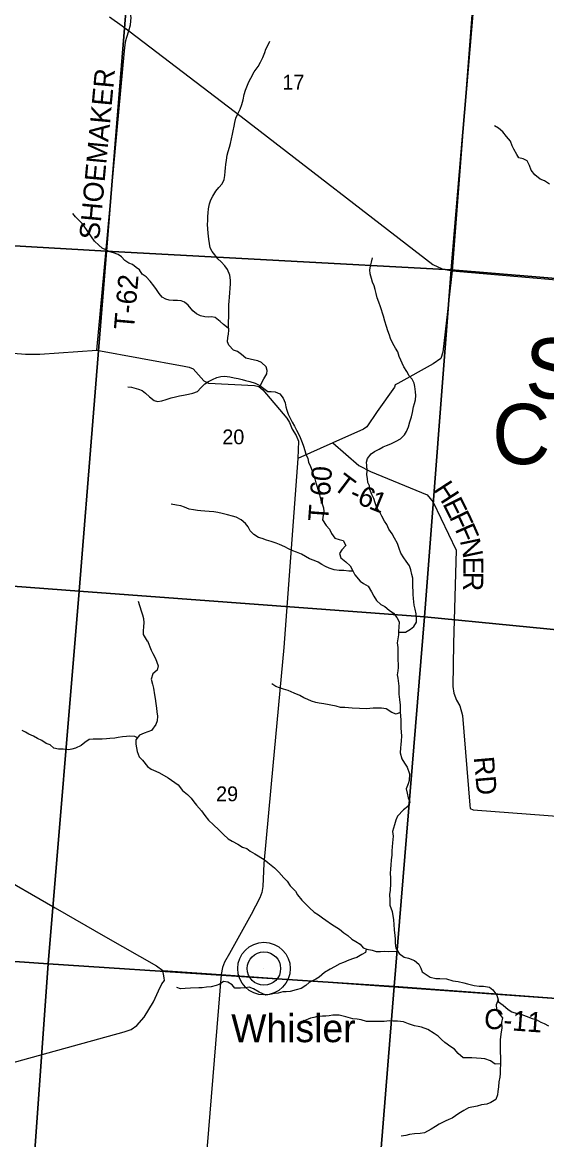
# Model space of a CAD drawing. Extents: x 0 to 42.5, y 0 to 22.
# Drawn here: x 5.708 to 6.449, y 16.014 to 17.595 of the extents above; entities that cross this region are included whole.
import ezdxf

# ---------------------------------------------------------------- set-up
doc = ezdxf.new("R2010")
doc.units = 0
for name, color, linetype in [('GM_X_County_Road', 7, 'Continuous'), ('GM_X_County_Road_Text', 7, 'Continuous'), ('GM_X_Minor_River', 7, 'Continuous'), ('GM_X_Section', 7, 'Continuous'), ('GM_X_Section_Text', 7, 'Continuous'), ('GM_X_State_Route', 7, 'Continuous'), ('GM_X_Township_Road', 7, 'Continuous'), ('GM_X_Township_Road_Text', 7, 'Continuous'), ('GM_X_Township_Text', 7, 'Continuous'), ('GM_X_Unincorporated', 7, 'Continuous'), ('GM_X_Unincorporated_Location', 7, 'Continuous'), ('GM_X_Unincorporated_Text', 7, 'Continuous')]:
    doc.layers.add(name, color=color, linetype=linetype)

msp = doc.modelspace()

# ---------------------------------------------------------------- linework, layer by layer
at = {"layer": 'GM_X_County_Road'}
for points in [[(5.2721, 16.5649), (5.3757, 16.5503), (5.3909, 16.5477), (5.4176, 16.535), (5.5094, 16.4825), (5.589, 16.437), (5.6659, 16.3931), (5.7544, 16.3418), (5.8254, 16.3009), (5.8975, 16.2597), (5.9069, 16.2533), (5.989, 16.2475)], [(5.989, 16.2475), (6.4831, 16.2121), (6.7307, 16.193), (7.222, 16.1571)]]:
    msp.add_lwpolyline(points, dxfattribs=at)
at = {"layer": 'GM_X_Minor_River'}
for points in [[(6.0442, 17.0807), (6.0496, 17.0905), (6.0538, 17.0973), (6.054, 17.1024), (6.0528, 17.1074), (6.046, 17.1135), (6.0412, 17.1158), (6.0364, 17.1166), (6.0303, 17.118), (6.024, 17.1195), (6.0179, 17.1247), (6.0121, 17.1291), (6.0068, 17.1309), (5.9999, 17.1379), (5.9982, 17.1427), (5.9986, 17.1488), (5.9994, 17.1537), (6, 17.1592), (5.9996, 17.1659), (5.9996, 17.1714), (6.0002, 17.1775), (6, 17.1843), (5.9998, 17.1896), (6, 17.1951), (6.0003, 17.2002), (6.0008, 17.2059), (6.0012, 17.212), (6.0018, 17.2185), (6.0024, 17.2247), (6.0024, 17.2302), (6.0015, 17.2373), (5.9981, 17.2453), (5.9944, 17.2501), (5.9893, 17.2558), (5.9845, 17.2604), (5.9801, 17.2657), (5.9763, 17.2705), (5.9738, 17.2758), (5.9725, 17.2817), (5.9718, 17.2882), (5.9708, 17.2964), (5.9701, 17.3027), (5.9699, 17.3087), (5.9701, 17.3146), (5.9703, 17.3201), (5.9707, 17.3253), (5.9713, 17.3311), (5.9726, 17.3378), (5.9747, 17.3438), (5.9772, 17.349), (5.9815, 17.3559), (5.9861, 17.361), (5.9907, 17.3665), (5.9934, 17.3724), (5.9945, 17.3783), (5.9949, 17.3836), (5.9953, 17.3887), (5.9959, 17.3936), (5.9965, 17.3999), (5.9978, 17.4069), (5.9992, 17.4119), (6.0009, 17.4181), (6.0025, 17.4234), (6.0036, 17.4299), (6.0052, 17.4367), (6.0063, 17.4414), (6.0075, 17.4477), (6.0085, 17.4532), (6.01, 17.4591), (6.0121, 17.4646), (6.0158, 17.4718), (6.0186, 17.4786), (6.0202, 17.4852), (6.0219, 17.4928), (6.0237, 17.4987), (6.0264, 17.5061), (6.0281, 17.5108), (6.031, 17.5159), (6.0356, 17.5246), (6.0413, 17.5324), (6.0446, 17.5386), (6.0479, 17.5452), (6.0507, 17.552), (6.0525, 17.5568), (6.0552, 17.5619), (6.0582, 17.5679)], [(6.4536, 17.366), (6.4463, 17.3705), (6.4402, 17.3728), (6.4327, 17.3789), (6.4274, 17.3856), (6.4253, 17.3921), (6.4221, 17.3989), (6.4163, 17.4018), (6.4102, 17.403), (6.4074, 17.408), (6.403, 17.4152), (6.4007, 17.4202), (6.3984, 17.4266), (6.3927, 17.4333), (6.3873, 17.4398), (6.3814, 17.4452), (6.3757, 17.4485)], [(5.9999, 17.161), (5.999, 17.1621), (5.9925, 17.1671), (5.9878, 17.1715), (5.9805, 17.177), (5.9757, 17.1782), (5.9707, 17.1777), (5.966, 17.1783), (5.96, 17.1796), (5.9541, 17.1823), (5.9492, 17.1866), (5.9425, 17.1944), (5.9373, 17.199), (5.9325, 17.2007), (5.9274, 17.201), (5.9214, 17.201), (5.9157, 17.2018), (5.9109, 17.203), (5.9058, 17.2059), (5.9016, 17.211), (5.8976, 17.2166), (5.894, 17.2221), (5.8886, 17.2284), (5.8829, 17.2349), (5.8775, 17.2386), (5.8735, 17.2445), (5.8688, 17.2481), (5.8638, 17.2523), (5.8584, 17.2541), (5.8531, 17.2579), (5.8481, 17.2631), (5.8434, 17.2663), (5.8369, 17.2687), (5.8319, 17.2702), (5.826, 17.2729), (5.821, 17.2752), (5.816, 17.2795), (5.8101, 17.2854), (5.8059, 17.2913), (5.8019, 17.2968), (5.7964, 17.3051), (5.7924, 17.31), (5.788, 17.3148), (5.7834, 17.3196), (5.7792, 17.3244)], [(6.2401, 16.732), (6.25, 16.7319), (6.2569, 16.7361), (6.2617, 16.7398), (6.2653, 16.7459), (6.2655, 16.7525), (6.265, 16.7579), (6.2635, 16.7645), (6.2623, 16.7702), (6.2612, 16.7797), (6.2606, 16.7852), (6.2605, 16.7906), (6.2601, 16.7957), (6.2603, 16.8012), (6.2601, 16.8082), (6.259, 16.8134), (6.2575, 16.82), (6.2554, 16.8257), (6.251, 16.8322), (6.2474, 16.8372), (6.243, 16.8437), (6.2411, 16.8503), (6.2384, 16.8574), (6.2344, 16.8648), (6.2308, 16.8711), (6.2262, 16.8778), (6.2232, 16.8841), (6.2201, 16.889), (6.2165, 16.8961), (6.2136, 16.9016), (6.2094, 16.9081), (6.207, 16.9148), (6.2049, 16.9213), (6.202, 16.9266), (6.1996, 16.9338), (6.1988, 16.9388), (6.1967, 16.9439), (6.196, 16.9494), (6.1952, 16.9546), (6.1954, 16.9608), (6.195, 16.9677), (6.1947, 16.9724), (6.1962, 16.9775), (6.2014, 16.9843), (6.2062, 16.9874), (6.2125, 16.9911), (6.2181, 16.9941), (6.2228, 16.9962), (6.2292, 16.9984), (6.2364, 17.002), (6.2428, 17.0055), (6.2483, 17.0112), (6.2512, 17.0161), (6.2543, 17.0223), (6.256, 17.0295), (6.2583, 17.0366), (6.2599, 17.043), (6.2612, 17.0506), (6.2626, 17.0557), (6.2639, 17.0608), (6.2643, 17.0667), (6.2641, 17.072), (6.2632, 17.0796), (6.2619, 17.0844), (6.2592, 17.0897), (6.2552, 17.0945), (6.2516, 17.1008), (6.2476, 17.1073), (6.2411, 17.1222), (6.2388, 17.1284), (6.2356, 17.1338), (6.2321, 17.1403), (6.2287, 17.1473), (6.2272, 17.1521), (6.2249, 17.1582), (6.2228, 17.1645), (6.2207, 17.1719), (6.2188, 17.1789), (6.2145, 17.1921), (6.2122, 17.1987), (6.2099, 17.205), (6.2082, 17.2113), (6.2067, 17.217), (6.2053, 17.2218), (6.2033, 17.2273), (6.2019, 17.2324), (6.2, 17.2391), (6.1995, 17.2448), (6.2002, 17.2497), (6.2018, 17.2554), (6.2031, 17.2618)], [(5.8573, 17.0793), (5.8623, 17.0787), (5.8722, 17.076), (5.8774, 17.0737), (5.8821, 17.07), (5.8879, 17.0651), (5.8942, 17.0597), (5.8993, 17.0583), (5.9051, 17.0594), (5.9114, 17.0611), (5.9183, 17.0633), (5.9248, 17.065), (5.9303, 17.0665), (5.9361, 17.0674), (5.943, 17.0688), (5.9493, 17.0699), (5.9556, 17.0724), (5.9602, 17.0778), (5.9663, 17.0835), (5.9713, 17.0867), (5.9767, 17.0895), (5.983, 17.0921), (5.9887, 17.0936), (5.9937, 17.0941), (6.0014, 17.0933), (6.0077, 17.0919), (6.013, 17.0907), (6.0188, 17.0896), (6.0237, 17.0882), (6.0295, 17.0868), (6.0371, 17.0843), (6.044, 17.0808), (6.0497, 17.0768), (6.0551, 17.0726), (6.0598, 17.0724), (6.0656, 17.0721), (6.0721, 17.069), (6.0767, 17.0629), (6.0795, 17.0565), (6.0806, 17.0509), (6.082, 17.0462), (6.0841, 17.0403), (6.0871, 17.034), (6.0898, 17.0292), (6.0928, 17.0235), (6.0955, 17.018), (6.0985, 17.0128), (6.101, 17.0075), (6.1037, 17.0004), (6.1054, 16.9953), (6.1075, 16.9892), (6.1088, 16.9837), (6.1119, 16.9776), (6.1128, 16.9724), (6.1157, 16.9665), (6.1179, 16.9604), (6.1198, 16.9538), (6.1215, 16.949), (6.1231, 16.9431), (6.125, 16.9374), (6.1269, 16.9311), (6.128, 16.9264), (6.1303, 16.9186), (6.1318, 16.9136), (6.1337, 16.9077), (6.1343, 16.9028), (6.1333, 16.8977), (6.1325, 16.891), (6.1377, 16.8828), (6.1422, 16.8776), (6.1451, 16.8715), (6.1499, 16.8649), (6.1558, 16.8631), (6.1619, 16.8617), (6.1653, 16.8545), (6.16, 16.8483), (6.1567, 16.8432), (6.1582, 16.8373), (6.1655, 16.8315), (6.1718, 16.8256), (6.1752, 16.8189), (6.1784, 16.813), (6.1855, 16.8042), (6.1903, 16.8009), (6.1972, 16.7969), (6.2017, 16.7891), (6.2052, 16.7828), (6.2088, 16.7769), (6.2149, 16.7713), (6.2208, 16.7682), (6.2267, 16.7633), (6.2327, 16.759), (6.2374, 16.7525), (6.2409, 16.7468), (6.2406, 16.7392), (6.2401, 16.7333), (6.24, 16.7282), (6.2381, 16.7171)], [(6.1756, 16.8182), (6.1746, 16.8181), (6.1695, 16.8184), (6.1626, 16.819), (6.1559, 16.8194), (6.1488, 16.8202), (6.1417, 16.8224), (6.1368, 16.8247), (6.1314, 16.8278), (6.1265, 16.831), (6.1209, 16.8332), (6.1142, 16.8355), (6.1028, 16.8424), (6.0957, 16.8451), (6.0903, 16.8472), (6.0842, 16.85), (6.0791, 16.8526), (6.0716, 16.8561), (6.0668, 16.8581), (6.06, 16.8604), (6.0531, 16.8621), (6.0472, 16.8643), (6.042, 16.866), (6.0353, 16.8702), (6.0303, 16.8754), (6.0275, 16.8811), (6.0237, 16.8859), (6.0176, 16.8909), (6.0105, 16.8947), (6.0051, 16.8963), (5.9981, 16.8981), (5.9908, 16.8998), (5.9843, 16.9012), (5.9789, 16.9022), (5.9724, 16.9028), (5.9661, 16.9032), (5.9606, 16.9035), (5.9556, 16.9039), (5.9499, 16.9049), (5.9441, 16.9062), (5.9371, 16.9088), (5.9319, 16.9105), (5.926, 16.9117), (5.9185, 16.9133)], [(5.8851, 16.7193), (5.8795, 16.7289), (5.8793, 16.7339), (5.8799, 16.7397), (5.8801, 16.7458), (5.8797, 16.7509), (5.8784, 16.7561), (5.8767, 16.7616), (5.8722, 16.7752)], [(5.885, 16.7196), (5.8903, 16.7067), (5.8927, 16.7017), (5.8965, 16.6949), (5.8982, 16.6896), (5.9003, 16.6844), (5.8989, 16.678), (5.8925, 16.6729), (5.8904, 16.6655), (5.8921, 16.6586), (5.8937, 16.6528), (5.8951, 16.6435), (5.8958, 16.6379), (5.8969, 16.6309), (5.8979, 16.6243), (5.8982, 16.6191), (5.899, 16.6131), (5.8988, 16.6066), (5.8967, 16.6015), (5.8908, 16.5928), (5.8803, 16.5889), (5.8735, 16.5864), (5.8685, 16.5796), (5.8687, 16.5735), (5.8704, 16.5631), (5.8734, 16.5557), (5.878, 16.5507), (5.8848, 16.5421), (5.8903, 16.5383), (5.8967, 16.5354), (5.902, 16.5331), (5.9141, 16.5261), (5.919, 16.5224), (5.9283, 16.5161), (5.9344, 16.5079), (5.9416, 16.5024), (5.9467, 16.4969), (5.9506, 16.4919), (5.9544, 16.4872), (5.9612, 16.4793), (5.966, 16.4727), (5.9714, 16.4658), (5.9782, 16.4595), (5.986, 16.4525), (5.9924, 16.4456), (5.9989, 16.4395), (6.0049, 16.4362), (6.0127, 16.432), (6.0193, 16.428), (6.0254, 16.4257), (6.0303, 16.4223), (6.0368, 16.4184), (6.05, 16.4104), (6.0553, 16.406), (6.0644, 16.3987), (6.0708, 16.3924), (6.078, 16.3846), (6.0824, 16.3795), (6.0867, 16.373), (6.0943, 16.3656), (6.0971, 16.3604), (6.1034, 16.3528), (6.1083, 16.3477), (6.1143, 16.3419), (6.1208, 16.3358), (6.1268, 16.3322), (6.1323, 16.3278), (6.1372, 16.3246), (6.145, 16.319), (6.1564, 16.3119), (6.1624, 16.3066), (6.1683, 16.3028), (6.174, 16.2978), (6.1795, 16.2942), (6.1859, 16.2905), (6.1901, 16.2854), (6.195, 16.2835), (6.2028, 16.2821), (6.2083, 16.2804), (6.2147, 16.2803), (6.2202, 16.2809), (6.2263, 16.2801), (6.2385, 16.2809)], [(6.2381, 16.7171), (6.2392, 16.7105), (6.2392, 16.704), (6.239, 16.6991), (6.2392, 16.6921), (6.2396, 16.687), (6.2395, 16.6822), (6.239, 16.6771), (6.2382, 16.6718), (6.2389, 16.667), (6.2402, 16.6558), (6.2406, 16.6505), (6.2402, 16.6443), (6.2415, 16.6365), (6.2423, 16.6289), (6.2424, 16.6241), (6.2422, 16.6188), (6.2434, 16.6078), (6.243, 16.6027), (6.2433, 16.596), (6.2437, 16.5911), (6.2442, 16.585), (6.2439, 16.5782), (6.2433, 16.5731), (6.2429, 16.5683), (6.2423, 16.5615), (6.2446, 16.5527), (6.2483, 16.5468), (6.2521, 16.5408), (6.2553, 16.5316), (6.2551, 16.5221), (6.2538, 16.5172), (6.2509, 16.5102), (6.252, 16.5041), (6.2537, 16.4975), (6.2558, 16.4916), (6.2533, 16.4855), (6.247, 16.4804), (6.2387, 16.4715), (6.236, 16.4659), (6.2343, 16.4594), (6.2316, 16.4499), (6.2323, 16.4433), (6.2314, 16.4338), (6.2306, 16.4228), (6.2306, 16.4164), (6.2296, 16.4099), (6.229, 16.4023), (6.2284, 16.397), (6.2282, 16.3907), (6.2284, 16.3843), (6.2284, 16.3763), (6.228, 16.3664), (6.2274, 16.3611), (6.2276, 16.3524), (6.2279, 16.3458), (6.231, 16.3368), (6.2328, 16.3252), (6.2332, 16.3184), (6.2339, 16.3108), (6.2347, 16.303), (6.235, 16.2975), (6.2354, 16.2922), (6.236, 16.2848), (6.2409, 16.2774), (6.2479, 16.2722), (6.2539, 16.2707), (6.2627, 16.2674), (6.2687, 16.2621), (6.2713, 16.2565), (6.2732, 16.2516), (6.2848, 16.2439), (6.2929, 16.2418), (6.2984, 16.2422), (6.3079, 16.2414), (6.3166, 16.2389), (6.3244, 16.2377), (6.3324, 16.2359), (6.3377, 16.2346), (6.347, 16.2321), (6.3538, 16.2313), (6.36, 16.2311), (6.3684, 16.2297), (6.3733, 16.2259), (6.3788, 16.2182), (6.3807, 16.2118), (6.3778, 16.2048), (6.3787, 16.1987), (6.3825, 16.1922), (6.3871, 16.1863), (6.3857, 16.1797), (6.3859, 16.1721), (6.3847, 16.1632), (6.3838, 16.1552), (6.3837, 16.1427), (6.3835, 16.1377), (6.3841, 16.1309), (6.3843, 16.1256), (6.3841, 16.1201), (6.3839, 16.1135), (6.3836, 16.1076)], [(6.2423, 16.6182), (6.2364, 16.6158), (6.2303, 16.6183), (6.2227, 16.6233), (6.2161, 16.6246), (6.2043, 16.6243), (6.1948, 16.6236), (6.1848, 16.6238), (6.1745, 16.6244), (6.1641, 16.6253), (6.1581, 16.6255), (6.152, 16.6274), (6.1342, 16.6305), (6.1277, 16.6315), (6.1228, 16.6323), (6.1171, 16.6342), (6.1116, 16.6365), (6.1059, 16.639), (6.1002, 16.6423), (6.0925, 16.6459), (6.0841, 16.6494), (6.0775, 16.6513), (6.0718, 16.6534), (6.0663, 16.6553), (6.0608, 16.659)], [(5.8707, 16.5825), (5.867, 16.5844), (5.86, 16.585), (5.8551, 16.5846), (5.8496, 16.5841), (5.8433, 16.5828), (5.8386, 16.582), (5.8319, 16.5815), (5.8272, 16.5811), (5.8209, 16.5808), (5.8143, 16.5808), (5.808, 16.5807), (5.8025, 16.5799), (5.7963, 16.576), (5.7913, 16.5715), (5.7834, 16.5677), (5.7782, 16.5664), (5.7735, 16.5653), (5.7659, 16.5663), (5.7591, 16.5665), (5.7526, 16.568), (5.7473, 16.5724), (5.7417, 16.5747), (5.7358, 16.5786), (5.7295, 16.5814), (5.7237, 16.5849), (5.7174, 16.5879), (5.7127, 16.5904), (5.7078, 16.5927)], [(6.1943, 16.2837), (6.1931, 16.2787), (6.1881, 16.2761), (6.1809, 16.2716), (6.1762, 16.2705), (6.1697, 16.268), (6.1623, 16.2648), (6.1572, 16.2626), (6.1492, 16.2583), (6.1433, 16.2551), (6.1352, 16.2505), (6.1278, 16.2439), (6.1228, 16.2411), (6.1137, 16.2362), (6.1088, 16.2319), (6.1021, 16.2279), (6.0953, 16.2261), (6.0869, 16.2236), (6.0812, 16.2231), (6.0765, 16.2231), (6.07, 16.2211), (6.0647, 16.2209), (6.0579, 16.2194), (6.0524, 16.2185), (6.0429, 16.2225), (6.035, 16.2275), (6.0289, 16.2298), (6.0234, 16.2287), (6.0164, 16.2283), (6.0084, 16.2282), (6.0048, 16.233), (5.9984, 16.2366), (5.9925, 16.2378), (5.9874, 16.2342), (5.9823, 16.2319), (5.9751, 16.2303), (5.9686, 16.2295), (5.9625, 16.229), (5.9574, 16.2286), (5.946, 16.2283), (5.9381, 16.228), (5.9318, 16.2276), (5.9265, 16.2292)], [(6.3806, 16.2121), (6.3814, 16.2089), (6.3879, 16.2043), (6.3952, 16.1979), (6.4002, 16.195), (6.4076, 16.1927), (6.4129, 16.1915), (6.4203, 16.1886), (6.429, 16.1855), (6.4347, 16.1838), (6.4411, 16.18), (6.4458, 16.1781), (6.4521, 16.1752)], [(6.3841, 16.1213), (6.3767, 16.1209), (6.3698, 16.1257), (6.3621, 16.1282), (6.357, 16.129), (6.3437, 16.1296), (6.3314, 16.1297), (6.3245, 16.1359), (6.3189, 16.1419), (6.3138, 16.1455), (6.3056, 16.1514), (6.3007, 16.1556), (6.2958, 16.1604), (6.2903, 16.1642), (6.2812, 16.1698), (6.2725, 16.1732), (6.2677, 16.174), (6.2626, 16.1752), (6.2543, 16.178), (6.2469, 16.1807), (6.2387, 16.1817), (6.2323, 16.1814), (6.2272, 16.182), (6.2196, 16.1811), (6.2038, 16.1813), (6.1947, 16.1812), (6.187, 16.1835), (6.1815, 16.1845), (6.1754, 16.1851), (6.1656, 16.1878), (6.1559, 16.1901), (6.1473, 16.1901), (6.142, 16.1894), (6.1373, 16.1885), (6.1326, 16.1885), (6.1255, 16.188), (6.1202, 16.187), (6.1155, 16.1857), (6.1066, 16.182), (6.105, 16.1824)], [(6.3836, 16.1076), (6.3831, 16.1024), (6.3819, 16.0956), (6.3815, 16.0888), (6.3806, 16.082), (6.3798, 16.0772), (6.3777, 16.0706), (6.3707, 16.0664), (6.365, 16.0644), (6.3574, 16.0633), (6.3513, 16.0616), (6.3388, 16.0588), (6.3323, 16.0552), (6.3251, 16.0511), (6.316, 16.0445), (6.3112, 16.0423), (6.3057, 16.04), (6.2974, 16.0359), (6.2924, 16.0325), (6.286, 16.0287), (6.2767, 16.0238), (6.2706, 16.0225), (6.2624, 16.0222), (6.2556, 16.0215), (6.2503, 16.0201), (6.2439, 16.0187)]]:
    msp.add_lwpolyline(points, dxfattribs=at)
at = {"layer": 'GM_X_Section'}
for points in [[(5.3699, 17.8309), (5.869, 17.7911), (5.8269, 17.2708), (5.3293, 17.2998), (5.3314, 17.3322)], [(5.869, 17.7911), (6.3574, 17.7514), (6.3142, 17.2447), (5.8269, 17.2708)], [(6.3574, 17.7514), (6.8654, 17.7064), (6.8214, 17.2026), (6.3142, 17.2447)], [(5.8269, 17.2708), (5.7883, 16.79), (5.2943, 16.8273), (5.3293, 17.2998)], [(6.3142, 17.2447), (6.2767, 16.7537), (5.7883, 16.79), (5.8269, 17.2708)], [(6.8214, 17.2026), (6.7762, 16.7046), (6.2767, 16.7537), (6.3142, 17.2447)], [(5.2939, 16.8234), (5.2943, 16.8273), (5.7883, 16.79), (5.7447, 16.2626), (5.2526, 16.2971), (5.2539, 16.306)], [(5.7883, 16.79), (6.2767, 16.7537), (6.2337, 16.2305), (5.7447, 16.2626)], [(6.2767, 16.7537), (6.7762, 16.7046), (6.7311, 16.1941), (6.2337, 16.2305)], [(5.7447, 16.2626), (5.709, 15.7681), (5.691, 15.7693), (5.2174, 15.8004), (5.2526, 16.2971)], [(6.2337, 16.2305), (6.1935, 15.7327), (6.1843, 15.7333), (5.709, 15.7681), (5.7447, 16.2626)], [(6.7311, 16.1941), (6.6857, 15.6968), (6.6766, 15.6974), (6.1935, 15.7327), (6.2337, 16.2305)]]:
    msp.add_lwpolyline(points, close=True, dxfattribs=at)
at = {"layer": 'GM_X_State_Route'}
for points in [[(5.8313, 17.6025), (5.8491, 17.5898), (5.8584, 17.5829), (5.8704, 17.5737)], [(5.8704, 17.5737), (6.0174, 17.4616), (6.2886, 17.2522), (6.3018, 17.2462), (6.3156, 17.2432), (6.8183, 17.2)]]:
    msp.add_lwpolyline(points, dxfattribs=at)
at = {"layer": 'GM_X_Township_Road'}
for p, q in [((6.355, 17.7497), (6.3156, 17.2432)), ((6.1472, 17), (6.0974, 16.9779))]:
    msp.add_line(p, q, dxfattribs=at)
for points in [[(5.8584, 17.5829), (5.861, 17.591), (5.8619, 17.6015), (5.8599, 17.6126), (5.8584, 17.6252), (5.8655, 17.7887), (5.892, 18.1007)], [(5.8133, 17.1309), (5.8524, 17.5544), (5.8532, 17.563), (5.8544, 17.5692), (5.8557, 17.574), (5.8584, 17.5829)], [(6.3156, 17.2432), (6.3024, 17.1279), (6.2999, 17.119), (6.2888, 17.1117), (6.2388, 17.0836), (6.2354, 17.0817), (6.2342, 17.0785), (6.2099, 17.0444), (6.1952, 17.0223), (6.1902, 17.0192), (6.1472, 17)], [(5.6252, 17.1322), (5.7124, 17.1253), (5.7327, 17.1252), (5.8133, 17.1309), (5.9367, 17.1083), (5.9441, 17.1069), (5.9496, 17.1045), (5.9647, 17.0876), (5.9711, 17.0845), (6.0362, 17.0811), (6.0426, 17.0795), (6.0479, 17.0747), (6.0822, 17.0349), (6.0858, 17.0286), (6.0898, 17.0192), (6.0954, 17.0104), (6.0983, 17.002), (6.0974, 16.9779)], [(6.1472, 17), (6.1839, 16.9679), (6.2005, 16.9592), (6.2804, 16.9263), (6.2888, 16.9159), (6.3213, 16.848), (6.3177, 16.7161), (6.3168, 16.6552), (6.3183, 16.6459), (6.3221, 16.6359), (6.3267, 16.6279), (6.3304, 16.6141), (6.3409, 16.4874), (6.3411, 16.4827), (6.3456, 16.4804), (6.5013, 16.469), (6.5036, 16.4658), (6.4831, 16.2121)], [(6.0974, 16.9779), (6.0777, 16.7102), (6.0623, 16.5428), (6.0493, 16.4045), (6.0483, 16.3721), (6.0469, 16.3637), (6.0437, 16.3559), (6.0316, 16.3327), (6.001, 16.2773), (5.9938, 16.2649), (5.991, 16.2575), (5.989, 16.2475)], [(5.239, 16.1137), (5.264, 16.1162), (5.3168, 16.1171), (5.3612, 16.1179), (5.4534, 16.1186), (5.4859, 16.1185), (5.5292, 16.115), (5.5903, 16.1112), (5.6252, 16.1066), (5.6364, 16.107), (5.8519, 16.1666), (5.8619, 16.1699), (5.8701, 16.1756), (5.8801, 16.1874), (5.8937, 16.2088), (5.9007, 16.2244), (5.9053, 16.2343), (5.9089, 16.2392), (5.9087, 16.2428), (5.9069, 16.2533)], [(5.989, 16.2475), (5.9553, 15.832), (5.954, 15.8198), (5.9515, 15.8164), (5.9358, 15.812), (5.9335, 15.8059), (5.9293, 15.7496)]]:
    msp.add_lwpolyline(points, dxfattribs=at)
at = {"layer": 'GM_X_Unincorporated'}
for radius in [0.0372, 0.0236]:
    msp.add_circle((6.0497, 16.256), radius, dxfattribs=at)
at = {"layer": 'GM_X_Unincorporated_Location'}
msp.add_line((6.0497, 16.256), (6.0497, 16.256), dxfattribs=at)

# ---------------------------------------------------------------- texts
at = {"layer": 'GM_X_County_Road_Text'}
msp.add_text('C-11', height=0.02841, rotation=355.865, dxfattribs=at).set_placement((6.3601, 16.1714))
at = {"layer": 'GM_X_Section_Text'}
for s, p in [('17', (6.0758, 17.4997)), ('20', (5.9908, 16.9978)), ('29', (5.982, 16.4928))]:
    msp.add_text(s, height=0.02093, rotation=0, dxfattribs=at).set_placement(p)
at = {"layer": 'GM_X_Township_Road_Text'}
for s, height, rotation, p in [('SHOEMAKER', 0.02841, 84.6956, (5.8167, 17.2863)), ('T-62', 0.02841, 85.0303, (5.8657, 17.1589)), ('T-60', 0.02841, 85.7632, (6.1404, 16.8879)), ('T', 0.0284, 322.9193, (6.1459, 16.936)), ('H', 0.0284, 303.0849, (6.2886, 16.934)), ('-', 0.0284, 335.2142, (6.1685, 16.9197)), ('6', 0.0284, 337.0367, (6.18, 16.9144)), ('1', 0.0284, 337.9611, (6.1966, 16.9074)), ('E', 0.0284, 296.2019, (6.3018, 16.9138)), ('F', 0.0284, 295.5716, (6.3111, 16.8949)), ('F', 0.0284, 293.674, (6.3193, 16.8778)), ('N', 0.0284, 281.9361, (6.3265, 16.8617)), ('E', 0.0284, 270.42, (6.3315, 16.8387)), ('R', 0.0284, 268.911, (6.3317, 16.8177)), ('RD', 0.02841, 274.9263, (6.3464, 16.555))]:
    msp.add_text(s, height=height, rotation=rotation, dxfattribs=at).set_placement(p)
at = {"layer": 'GM_X_Township_Text'}
for s, p in [('SALT', (6.4189, 17.0625)), ('CREEK', (6.3724, 16.9697))]:
    msp.add_text(s, height=0.08523, rotation=0, dxfattribs=at).set_placement(p)
at = {"layer": 'GM_X_Unincorporated_Text'}
msp.add_text('Whisler', height=0.03949, rotation=0, dxfattribs=at).set_placement((6.0033, 16.1519))

doc.saveas('drawing.dxf')
